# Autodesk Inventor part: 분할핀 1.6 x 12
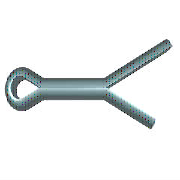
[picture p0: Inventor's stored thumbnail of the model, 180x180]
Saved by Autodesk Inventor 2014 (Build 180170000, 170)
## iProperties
IsCustomPart: 1
Created: 2012-02
Part Number: 분할핀 1.6 x 12
Material: 강철, 연강
Description: 분할 핀
Document SubType Name: Modeling
Standard: KS B 1321
Designer: mduedu
Standards Organization: KS
Language: ko-KR
Size Designation: 1.6 x  12
Categories: <MemberInstance><Categories><Category DisplayName="조임쇠" InternalName="e4da775c-781d-43d5-af7c-5136215cf5a6" Mnemonic="FSTN"><Category DisplayName="핀" InternalNa
Density: 1 g/cm^3
Appearance: 강철
Author: mduedu
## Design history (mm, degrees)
sketch "스케치1"
  geometry: L1 (0, 0.7)-(7, 0.7); L2 (0, -0.7)-(7, -0.7); L3 (7, 0.7)-(12, 2.616); L4 (12, 2.616)-(12.234, 2.005); L5 (12.234, 2.005)-(7, 0); L6 (7, 0)-(14.734, -2.963); L7 (14.734, -2.963)-(14.5, -3.573); L8 (14.5, -3.573)-(7, -0.7); L9 (0, 0)-(-1.528, -0.645); L10 (0, 0)-(-1.528, 0.645); L11 (0, 0.7)-(0, -0.7); L12 (0, 0.7)-(-1.204, 1.267); L13 (0, -0.7)-(-1.204, -1.267); L14 (-3.2, 0)-(7, 0); L15 (7, 0.7)-(7, -0.7); A1 r 1.4 centre (-1.8, 0) between (-1.204, 1.267) and (-1.204, -1.267); A2 r 0.7 centre (-1.8, 0) between (-1.528, 0.645) and (-1.528, -0.645); 1 further point
  constraints: 30 end point, 5 point on circle, 4 parallel, 4 perpendicular, 4 point on line, 4 tangent, 2 centre point, 2 midpoint, 1 coincident, 1 horizontal
  dimensions: "d0" = 7 distance of L1.start L1.end (= MSIAB); "d1" = 12 horizontal distance of L1.start L3.end (= SNLG); "d2" = 159.037 deg angle of L1 L3; "d3" = 159.037 deg angle of L2 L8; "d4" = 2.5 horizontal distance of L3.end L7.end (= LGDIF); "d5" = 0.7 radius of A2 (= -0.5 x SNND1 + 0.5 x KBR); "d6" = 1.4 radius of A1 (= 0.5 x KBR); "d7" = 0.7 distance from line of L1 L9.start (= 0.5 x SNND1); "d8" = 0.7 distance between parallel lines of L2 L14 (= 0.5 x SNND1); "d9" = 1.8 distance from line of L11 A1.centre (= KOL - 0.5 x KBR)
extrude "본체" new body sketch "스케치1" stored distance "d10" = 1.4 (= SNND1); taper "d11" = 0 deg
workaxis "Work Axis1"
workplane "Work Plane1"
workplane "Work Plane3"
node "작업 평면4"
  node "작업 평면3"
body "Solid1"
fillet "모깎기" dims "d12" = 0.49 (= 0.35 x SNND1)
other parameters: "SNND" = 1.6 [user parameter], "SNLG" = 12 [user parameter; used in 1 equation term], "SNND1" = 1.4 [user parameter; used in 5 equation terms], "KBR" = 2.8 [user parameter; used in 3 equation terms], "KOL" = 3.2 [user parameter; used in 1 equation term], "LGDIF" = 2.5 [user parameter; used in 1 equation term], "MSIAB" = 7 [user parameter; used in 1 equation term], "d15" = 0, "d16" = 0, "d17" = 0, "NNDMAX" = 7 [user parameter], "DSH" = 6 [user parameter], "NNDMIN" = 5.5 [user parameter], "d18" = 0, "d19" = -3.25
